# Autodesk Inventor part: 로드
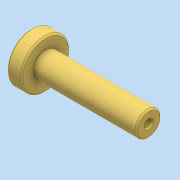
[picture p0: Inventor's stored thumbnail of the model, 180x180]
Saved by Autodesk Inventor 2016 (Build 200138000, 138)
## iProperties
Created: 2024-09
Part Number: 로드
Material: 일반
Document SubType Name: Modeling
Designer: pc-7
Density: 1 g/cm^3
Appearance: 기본값
Author: jhkim
Sending System: Autodesk Inventor 2025
Preprocessor: ST-DEVELOPER v20
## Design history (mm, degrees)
node "로드1"
node "솔리드2"
node "솔리드1"
